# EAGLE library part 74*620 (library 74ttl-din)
Octal BUS TRANSCEIVER, 3-state
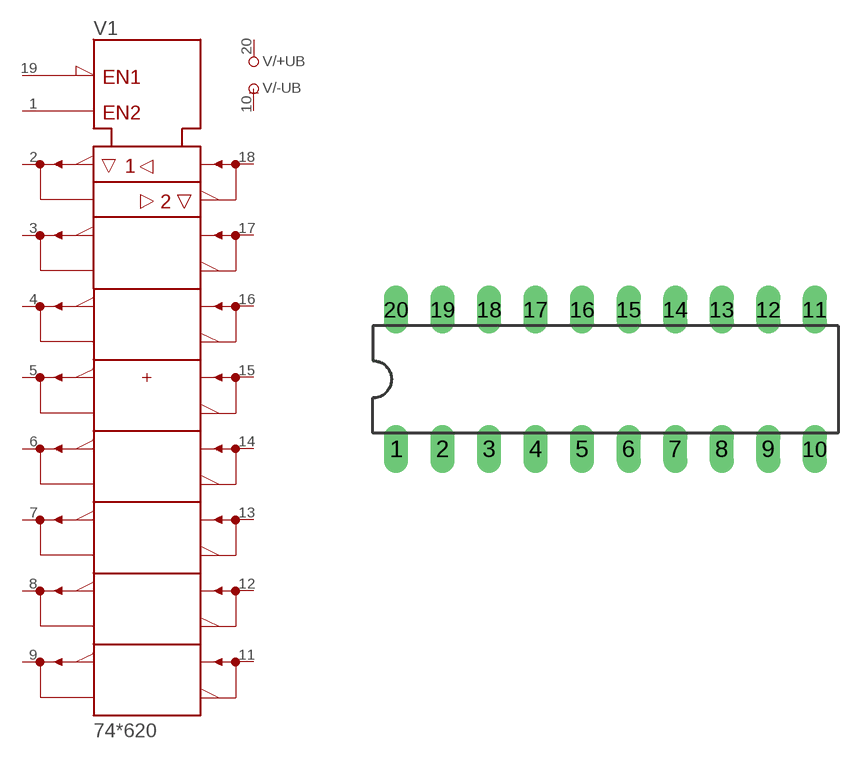
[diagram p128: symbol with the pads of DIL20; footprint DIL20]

Designator prefix V; gates /+UB=+UB /-UB=-UB 1=620

## 74620N  [DIL20]
1  1:GAB  in
2  1:A1
3  1:A2
4  1:A3
5  1:A4
6  1:A5
7  1:A6
8  1:A7
9  1:A8
10  /-UB:-UB  pwr
11  1:B8
12  1:B7
13  1:B6
14  1:B5
15  1:B4
16  1:B3
17  1:B2
18  1:B1
19  1:G\BA  in
20  /+UB:+UB  pwr

## Footprint DIL20 (pad centres in mm)
Dual In Line Package
drill 0.813 long: 1 -11.43,-3.81; 2 -8.89,-3.81; 3 -6.35,-3.81; 4 -3.81,-3.81; 5 -1.27,-3.81; 6 1.27,-3.81; 7 3.81,-3.81; 8 6.35,-3.81; 9 8.89,-3.81; 10 11.43,-3.81; 11 11.43,3.81; 12 8.89,3.81; 13 6.35,3.81; 14 3.81,3.81; 15 1.27,3.81; 16 -1.27,3.81; 17 -3.81,3.81; 18 -6.35,3.81; 19 -8.89,3.81; 20 -11.43,3.81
